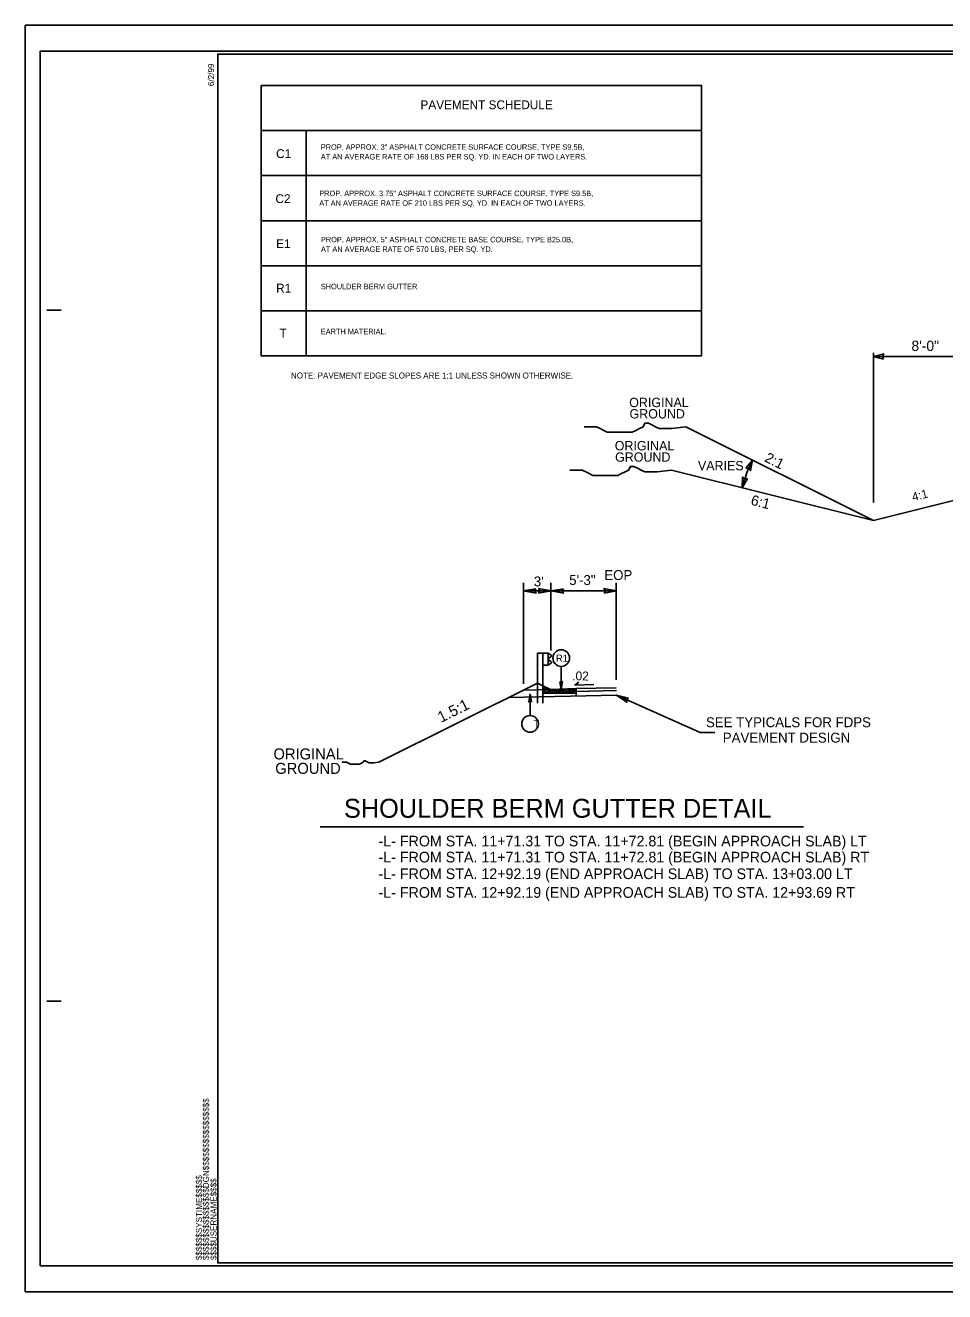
# Model space of a CAD drawing. Extents: x 573980 to 574178, y -53449 to -53334.
# Drawn here: x 573980.1 to 574063.6, y -53449 to -53334 of the extents above; entities that cross this region are included whole.
import ezdxf

# ---------------------------------------------------------------- set-up
doc = ezdxf.new("R2010")
doc.units = 0
for name, color, linetype in [('Old_Level_1', 7, 'Continuous'), ('Old_Level_11', 7, 'Continuous'), ('Prop Conc Shoulder Berm Gutter', 7, 'Continuous'), ('Prop Dimension Text', 7, 'Continuous'), ('Prop Pavement Schedule Description CELL', 7, 'Continuous'), ('Sheet Plot Border Inside CELL', 7, 'Continuous'), ('Sheet Plot Border Outside CELL', 7, 'Continuous'), ('Sheet Typical CELL', 7, 'Continuous'), ('Typical Slope Point Local CELL', 7, 'Continuous'), ('Typical Terminator CELL', 7, 'Continuous'), ('Typical Text General CELL', 7, 'Continuous')]:
    doc.layers.add(name, color=color, linetype=linetype)

# ---------------------------------------------------------------- blocks, each defined once
blk = doc.blocks.new('TERMINATOR')
at = {"layer": 'Typical Terminator CELL'}
blk.add_lwpolyline([(-0.469, 0.081), (0, 0), (-0.471, -0.083), (-0.411, 0)], close=True, dxfattribs=at)

msp = doc.modelspace()

# ---------------------------------------------------------------- linework, layer by layer
at = {"layer": 'Old_Level_1'}
msp.add_line((574006.85, -53406.8), (574050.73, -53406.8), dxfattribs=at)
at = {"layer": 'Prop Conc Shoulder Berm Gutter'}
for p, q in [((574027.06, -53391.01), (574026.59, -53391.01)), ((574026.59, -53391.01), (574026.59, -53393.39)), ((574027.06, -53391.01), (574027.06, -53393.39)), ((574027.06, -53391.01), (574027.54, -53391.01)), ((574027.54, -53391.01), (574027.54, -53392.12)), ((574027.54, -53391.01), (574027.82, -53391.2)), ((574027.54, -53391.52), (574027.82, -53391.33)), ((574027.54, -53391.56), (574027.54, -53391.52)), ((574027.54, -53391.56), (574027.54, -53391.61)), ((574027.54, -53391.61), (574027.82, -53391.8)), ((574027.06, -53392.12), (574027.54, -53392.12)), ((574027.54, -53392.12), (574027.82, -53391.93)), ((574028.74, -53392.23), (574028.74, -53394.32)), ((574012.19, -53400.94), (574026.59, -53393.74)), ((574026.59, -53393.39), (574026.59, -53395.58)), ((574027.06, -53393.98), (574026.59, -53393.74)), ((574027.06, -53393.39), (574027.06, -53395.58)), ((574027.06, -53393.98), (574027.76, -53394.33)), ((574027.06, -53394.66), (574027.06, -53393.98)), ((574029.97, -53393.92), (574030.34, -53393.67)), ((574031.71, -53393.88), (574029.97, -53393.92)), ((574023.99, -53395.05), (574033.76, -53394.83)), ((574025.32, -53394.38), (574027.76, -53394.33)), ((574025.91, -53396.7), (574025.91, -53394.74)), ((574030.09, -53394.66), (574027.06, -53394.66)), ((574027.26, -53394.33), (574027.27, -53394.4)), ((574027.38, -53394.36), (574027.26, -53394.33)), ((574027.27, -53394.4), (574027.38, -53394.36)), ((574027.53, -53394.58), (574027.58, -53394.48)), ((574027.66, -53394.54), (574027.53, -53394.58)), ((574027.58, -53394.48), (574027.66, -53394.54)), ((574030.09, -53394.25), (574027.76, -53394.33)), ((574027.85, -53394.58), (574027.9, -53394.49)), ((574027.99, -53394.55), (574027.85, -53394.58)), ((574027.9, -53394.49), (574027.99, -53394.55)), ((574028.24, -53394.54), (574028.31, -53394.44)), ((574028.34, -53394.53), (574028.24, -53394.54)), ((574028.31, -53394.44), (574028.34, -53394.53)), ((574028.53, -53394.58), (574028.58, -53394.48)), ((574028.66, -53394.54), (574028.53, -53394.58)), ((574028.58, -53394.48), (574028.66, -53394.54)), ((574028.84, -53394.47), (574028.89, -53394.38)), ((574028.97, -53394.44), (574028.84, -53394.47)), ((574028.89, -53394.38), (574028.97, -53394.44)), ((574029.24, -53394.54), (574029.31, -53394.44)), ((574029.34, -53394.53), (574029.24, -53394.54)), ((574029.31, -53394.44), (574029.34, -53394.53)), ((574029.53, -53394.58), (574029.58, -53394.48)), ((574029.66, -53394.54), (574029.53, -53394.58)), ((574029.58, -53394.48), (574029.66, -53394.54)), ((574029.88, -53394.41), (574029.93, -53394.32)), ((574030.02, -53394.38), (574029.88, -53394.41)), ((574029.93, -53394.32), (574030.02, -53394.38)), ((574030.09, -53394.25), (574033.74, -53394.17)), ((574030.09, -53394.25), (574030.09, -53394.66)), ((574030.09, -53394.25), (574030.09, -53394.91)), ((574030.09, -53394.5), (574033.75, -53394.42)), ((574033.76, -53394.83), (574041.34, -53398.22)), ((574042.7, -53398.22), (574041.34, -53398.22))]:
    msp.add_line(p, q, dxfattribs=at)
for points in [[(574026.44, -53385.17), (574025.32, -53385.36), (574026.45, -53385.56), (574026.3, -53385.36)], [(574026.69, -53385.56), (574027.82, -53385.36), (574026.69, -53385.16), (574026.83, -53385.36)], [(574028.94, -53385.17), (574027.82, -53385.36), (574028.95, -53385.56), (574028.81, -53385.36)], [(574032.63, -53385.56), (574033.75, -53385.36), (574032.62, -53385.16), (574032.76, -53385.36)], [(574028.62, -53393.62), (574028.74, -53394.32), (574028.86, -53393.61), (574028.74, -53393.7)], [(574026.03, -53395.44), (574025.91, -53394.74), (574025.79, -53395.45), (574025.91, -53395.36)], [(574034.86, -53395.12), (574033.76, -53394.83), (574034.7, -53395.48), (574034.66, -53395.24)]]:
    msp.add_lwpolyline(points, close=True, dxfattribs=at)
msp.add_lwpolyline([(574012.19, -53400.94), (574011.72, -53401), (574011.6, -53401), (574011.42, -53401), (574011.3, -53401), (574011.19, -53400.94), (574011.07, -53400.88), (574010.95, -53400.82), (574010.83, -53400.82), (574010.77, -53400.94), (574010.65, -53401), (574010.54, -53401.06), (574010.42, -53401.12), (574010.3, -53401.12), (574010.18, -53401.12), (574010.06, -53401.12), (574009.94, -53401.12), (574009.83, -53401.12), (574009.71, -53401.12), (574009.59, -53401.12), (574009.47, -53401.06), (574009.35, -53401), (574009.23, -53400.94), (574009.06, -53400.94), (574008.94, -53400.94), (574008.82, -53400.94)], dxfattribs=at)
for centre, radius in [((574028.74, -53391.47), 0.757), ((574027.12, -53394.07), 0.00643), ((574027.11, -53394.38), 0.00643), ((574027.12, -53394.59), 0.00643), ((574027.13, -53394.22), 0.00643), ((574027.18, -53394.47), 0.00643), ((574027.2, -53394.26), 0.00643), ((574027.2, -53394.34), 0.00643), ((574027.24, -53394.61), 0.00643), ((574027.28, -53394.51), 0.00643), ((574027.29, -53394.16), 0.00643), ((574027.29, -53394.49), 0.00643), ((574027.31, -53394.33), 0.00643), ((574027.31, -53394.45), 0.00643), ((574027.33, -53394.25), 0.00643), ((574027.36, -53394.29), 0.00643), ((574027.38, -53394.6), 0.00643), ((574027.4, -53394.21), 0.00643), ((574027.43, -53394.4), 0.00643), ((574027.46, -53394.63), 0.00643), ((574027.46, -53394.51), 0.00643), ((574027.49, -53394.28), 0.00643), ((574027.51, -53394.39), 0.00643), ((574027.59, -53394.41), 0.00643), ((574027.59, -53394.62), 0.00643), ((574027.62, -53394.31), 0.00643), ((574027.67, -53394.47), 0.00643), ((574027.72, -53394.46), 0.00643), ((574027.73, -53394.38), 0.00643), ((574027.76, -53394.57), 0.00643), ((574027.78, -53394.41), 0.00643), ((574027.81, -53394.34), 0.00643), ((574027.84, -53394.53), 0.00643), ((574027.9, -53394.38), 0.00643), ((574027.94, -53394.37), 0.00643), ((574027.95, -53394.45), 0.00643), ((574027.98, -53394.62), 0.00643), ((574028.05, -53394.46), 0.00643), ((574028.06, -53394.38), 0.00643), ((574028.09, -53394.57), 0.00643), ((574028.1, -53394.41), 0.00643), ((574028.12, -53394.43), 0.00643), ((574028.17, -53394.54), 0.00643), ((574028.16, -53394.62), 0.00643), ((574028.18, -53394.44), 0.00643), ((574028.24, -53394.49), 0.00643), ((574028.27, -53394.38), 0.00643), ((574028.27, -53394.62), 0.00643), ((574028.34, -53394.35), 0.00643), ((574028.34, -53394.47), 0.00643), ((574028.41, -53394.59), 0.00643), ((574028.45, -53394.43), 0.00643), ((574028.47, -53394.36), 0.00643), ((574028.48, -53394.52), 0.00643), ((574028.58, -53394.38), 0.00643), ((574028.59, -53394.62), 0.00643), ((574028.67, -53394.47), 0.00643), ((574028.71, -53394.32), 0.00643), ((574028.72, -53394.46), 0.00643), ((574028.73, -53394.38), 0.00643), ((574028.76, -53394.57), 0.00643), ((574028.78, -53394.41), 0.00643), ((574028.83, -53394.35), 0.00643), ((574028.84, -53394.53), 0.00643), ((574028.86, -53394.63), 0.00643), ((574028.93, -53394.51), 0.00643), ((574028.96, -53394.31), 0.00643), ((574028.98, -53394.62), 0.00643), ((574029.01, -53394.54), 0.00643), ((574029.05, -53394.46), 0.00643), ((574029.06, -53394.38), 0.00643), ((574029.09, -53394.57), 0.00643), ((574029.1, -53394.41), 0.00643), ((574029.12, -53394.43), 0.00643), ((574029.11, -53394.62), 0.00643), ((574029.16, -53394.31), 0.00643), ((574029.17, -53394.54), 0.00643), ((574029.24, -53394.49), 0.00643), ((574029.26, -53394.36), 0.00643), ((574029.27, -53394.38), 0.00643), ((574029.27, -53394.62), 0.00643), ((574029.34, -53394.47), 0.00643), ((574029.35, -53394.3), 0.00643), ((574029.36, -53394.62), 0.00643), ((574029.42, -53394.35), 0.00643), ((574029.43, -53394.53), 0.00643), ((574029.45, -53394.43), 0.00643), ((574029.51, -53394.48), 0.00643), ((574029.5, -53394.6), 0.00643), ((574029.58, -53394.38), 0.00643), ((574029.59, -53394.36), 0.00643), ((574029.59, -53394.62), 0.00643), ((574029.65, -53394.29), 0.00643), ((574029.67, -53394.47), 0.00643), ((574029.68, -53394.61), 0.00643), ((574029.72, -53394.46), 0.00643), ((574029.73, -53394.38), 0.00643), ((574029.74, -53394.29), 0.00643), ((574029.77, -53394.57), 0.00643), ((574029.78, -53394.41), 0.00643), ((574029.81, -53394.34), 0.00643), ((574029.84, -53394.53), 0.00643), ((574029.88, -53394.46), 0.00643), ((574029.89, -53394.28), 0.00643), ((574029.9, -53394.59), 0.00643), ((574029.97, -53394.5), 0.00643), ((574030.04, -53394.28), 0.00643), ((574030.04, -53394.61), 0.00643), ((574030.05, -53394.46), 0.00643), ((574030.06, -53394.38), 0.00643), ((574025.91, -53397.45), 0.757)]:
    msp.add_circle(centre, radius, dxfattribs=at)
for centre, radius, start, end in [((574027.78, -53391.26), 0.0743, 304.9888, 54.997), ((574027.78, -53391.86), 0.0743, 304.9634, 54.9941), ((574027.16, -53394.18), 0.00643, 311.0057, 48.9943), ((574027.78, -53394.66), 0.00643, 49.2889, 130.7111), ((574028.1, -53394.34), 0.00643, 209.9612, 270.0259), ((574028.26, -53394.36), 0.00643, 208.3343, 333.6652), ((574028.45, -53394.66), 0.00643, 21.9976, 158.0024), ((574028.59, -53394.36), 0.00643, 126.5832, 55.4163), ((574028.78, -53394.66), 0.00643, 49.2889, 130.7111), ((574029.1, -53394.34), 0.00643, 190.5183, 351.4812), ((574029.45, -53394.66), 0.00643, 21.9976, 158.0024), ((574029.48, -53394.34), 0.00643, 172.1997, 9.7998), ((574029.78, -53394.66), 0.00643, 49.2889, 130.7111), ((574030.09, -53394.57), 0.00643, 127.9938, 232.0062)]:
    msp.add_arc(centre, radius, start, end, dxfattribs=at)
at = {"layer": 'Prop Dimension Text'}
for p, q in [((574057.08, -53377.35), (574057.08, -53363.73)), ((574057.08, -53364.07), (574106.45, -53364.07)), ((574025.32, -53393.8), (574025.32, -53384.64)), ((574027.8, -53390.79), (574027.8, -53384.64)), ((574033.74, -53393.45), (574033.74, -53384.64)), ((574025.32, -53385.36), (574027.82, -53385.36)), ((574033.75, -53385.36), (574027.82, -53385.36))]:
    msp.add_line(p, q, dxfattribs=at)
msp.add_arc((574057.08, -53378.97), 12.27, 153.4349, 165.9638, dxfattribs=at)
at = {"layer": 'Prop Pavement Schedule Description CELL'}
msp.add_line((574001.48, -53364.01), (574001.48, -53364.01), dxfattribs=at)
msp.add_lwpolyline([(574001.48, -53339.46), (574041.48, -53339.46), (574041.48, -53343.55), (574001.48, -53343.55)], close=True, dxfattribs=at)
for points in [[(574005.57, -53347.64), (574001.48, -53347.64), (574001.48, -53343.55), (574041.48, -53343.55), (574041.48, -53347.64), (574005.57, -53347.64), (574005.57, -53343.55)], [(574005.57, -53351.74), (574001.48, -53351.74), (574001.48, -53347.64), (574041.48, -53347.64), (574041.48, -53351.74), (574005.57, -53351.74), (574005.57, -53347.64)], [(574005.57, -53355.83), (574001.48, -53355.83), (574001.48, -53351.74), (574041.48, -53351.74), (574041.48, -53355.83), (574005.57, -53355.83), (574005.57, -53351.74)], [(574005.57, -53359.92), (574001.48, -53359.92), (574001.48, -53355.83), (574041.48, -53355.83), (574041.48, -53359.92), (574005.57, -53359.92), (574005.57, -53355.83)], [(574005.57, -53364.01), (574001.48, -53364.01), (574001.48, -53359.92), (574041.48, -53359.92), (574041.48, -53364.01), (574005.57, -53364.01), (574005.57, -53359.92)]]:
    msp.add_lwpolyline(points, dxfattribs=at)
at = {"layer": 'Sheet Plot Border Inside CELL'}
msp.add_lwpolyline([(574155.75, -53336.33), (573981.44, -53336.33), (573981.44, -53446.69), (574155.75, -53446.69)], close=True, dxfattribs=at)
at = {"layer": 'Sheet Plot Border Outside CELL'}
msp.add_lwpolyline([(574156.22, -53333.98), (573980.08, -53333.98), (573980.08, -53449.04), (574156.22, -53449.04)], close=True, dxfattribs=at)
at = {"layer": 'Sheet Typical CELL'}
for p, q in [((573982.02, -53359.87), (573983.32, -53359.87)), ((573982.02, -53422.63), (573983.32, -53422.63)), ((573997.55, -53446.42), (573997.55, -53446.42)), ((573997.55, -53446.42), (573997.55, -53446.42)), ((573997.55, -53446.42), (573997.55, -53446.42)), ((573997.55, -53446.42), (573997.55, -53446.42)), ((573997.55, -53446.42), (573997.55, -53446.42)), ((573997.55, -53446.42), (573997.55, -53446.42))]:
    msp.add_line(p, q, dxfattribs=at)
msp.add_lwpolyline([(574154.44, -53336.6), (573997.55, -53336.6), (573997.55, -53446.42), (574154.44, -53446.42)], close=True, dxfattribs=at)
msp.add_lwpolyline([(574001.47, -53446.42), (574001.47, -53446.42)], dxfattribs=at)
at = {"layer": 'Typical Slope Point Local CELL'}
for p in [(574040.06, -53370.46), (574038.75, -53374.39), (574067.08, -53376.47)]:
    msp.add_line(p, (574057.08, -53378.97), dxfattribs=at)
for points in [[(574040.06, -53370.46), (574038.76, -53370.62), (574038.44, -53370.62), (574037.95, -53370.62), (574037.63, -53370.62), (574037.3, -53370.46), (574036.98, -53370.29), (574036.65, -53370.13), (574036.33, -53370.13), (574036.17, -53370.46), (574035.84, -53370.62), (574035.52, -53370.78), (574035.19, -53370.94), (574034.87, -53370.94), (574034.55, -53370.94), (574034.22, -53370.94), (574033.9, -53370.94), (574033.57, -53370.94), (574033.25, -53370.94), (574032.92, -53370.94), (574032.6, -53370.78), (574032.28, -53370.62), (574031.95, -53370.46), (574031.47, -53370.46), (574031.14, -53370.46), (574030.82, -53370.46)], [(574038.75, -53374.39), (574037.45, -53374.55), (574037.13, -53374.55), (574036.64, -53374.55), (574036.32, -53374.55), (574035.99, -53374.39), (574035.67, -53374.22), (574035.34, -53374.06), (574035.02, -53374.06), (574034.86, -53374.39), (574034.53, -53374.55), (574034.21, -53374.71), (574033.88, -53374.87), (574033.56, -53374.87), (574033.24, -53374.87), (574032.91, -53374.87), (574032.59, -53374.87), (574032.26, -53374.87), (574031.94, -53374.87), (574031.61, -53374.87), (574031.29, -53374.71), (574030.97, -53374.55), (574030.64, -53374.39), (574030.16, -53374.39), (574029.83, -53374.39), (574029.51, -53374.39)]]:
    msp.add_lwpolyline(points, dxfattribs=at)

# ---------------------------------------------------------------- block references
at = {"layer": 'Old_Level_11'}
for p, xscale, yscale, rotation in [((574057.08, -53364.07), 1.9883351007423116, 2.853881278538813, 180), ((574046.11, -53373.48), 1.9883351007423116, 2.853881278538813, 65.2036293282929), ((574045.18, -53375.99), 1.9883351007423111, 2.853881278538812, -106.02476566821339)]:
    msp.add_blockref('TERMINATOR', p, dxfattribs=dict(at, xscale=xscale, yscale=yscale, rotation=rotation))

# ---------------------------------------------------------------- texts
at = {"layer": 'Old_Level_1'}
for s, p in [('ORIGINAL ', (574034.91, -53368.67)), ('GROUND', (574034.94, -53369.7)), ('ORIGINAL ', (574033.6, -53372.6)), ('GROUND', (574033.63, -53373.63)), ('VARIES', (574041.15, -53374.41))]:
    msp.add_text(s, height=0.846, dxfattribs=at).set_placement(p)
at = {"layer": 'Prop Conc Shoulder Berm Gutter'}
for s, height, p in [('R1', 0.65, (574028.25, -53391.81)), ('SEE TYPICALS FOR FDPS ', 0.9, (574041.88, -53397.75)), ('PAVEMENT DESIGN', 0.9, (574043.41, -53399.15)), ('ORIGINAL', 1, (574002.61, -53400.68)), ('GROUND', 1, (574002.77, -53401.99)), ('SHOULDER BERM GUTTER DETAIL', 1.719, (574009.01, -53405.98)), ('-L- FROM STA. 11+71.31 TO STA. 11+72.81 (BEGIN APPROACH SLAB) LT', 0.9669, (574012.15, -53408.58)), ('-L- FROM STA. 11+71.31 TO STA. 11+72.81 (BEGIN APPROACH SLAB) RT', 0.9669, (574012.15, -53410.04)), ('-L- FROM STA. 12+92.19 (END APPROACH SLAB) TO STA. 13+03.00 LT', 0.9669, (574012.15, -53411.55)), ('-L- FROM STA. 12+92.19 (END APPROACH SLAB) TO STA. 12+93.69 RT', 0.9669, (574012.15, -53413.25))]:
    msp.add_text(s, height=height, dxfattribs=at).set_placement(p)
for s, height, rotation, p in [('.02', 0.81, 358.7448, (574029.73, -53393.48)), ('1.5:1', 1, 26.5651, (574017.83, -53397.36)), ('T', 0.65, 360, (574026.21, -53397.75))]:
    msp.add_text(s, height=height, rotation=rotation, dxfattribs=at).set_placement(p)
at = {"layer": 'Prop Dimension Text'}
for s, height, p in [('8\'-0"', 0.938, (574060.54, -53363.57)), ('EOP', 0.9, (574032.65, -53384.38)), ("3'", 0.9, (574026.25, -53384.96)), ('5\'-3"', 0.9, (574029.46, -53384.83))]:
    msp.add_text(s, height=height, dxfattribs=at).set_placement(p)
at = {"layer": 'Prop Pavement Schedule Description CELL'}
for s, height, p in [('PAVEMENT SCHEDULE', 0.8, (574015.96, -53341.6)), ('C1', 0.8, (574002.85, -53346.04)), ('AT AN AVERAGE RATE OF 168 LBS PER SQ. YD. IN EACH OF TWO LAYERS.', 0.5, (574006.91, -53346.17)), ('PROP. APPROX. 3" ASPHALT CONCRETE SURFACE COURSE, TYPE S9.5B,', 0.5, (574006.91, -53345.29)), ('PROP. APPROX. 3.75" ASPHALT CONCRETE SURFACE COURSE, TYPE S9.5B,', 0.5, (574006.77, -53349.5)), ('C2', 0.8, (574002.79, -53350.13)), ('AT AN AVERAGE RATE OF 210 LBS PER SQ. YD. IN EACH OF TWO LAYERS.', 0.5, (574006.77, -53350.38)), ('E1', 0.8, (574002.85, -53354.22)), ('PROP. APPROX. 5" ASPHALT CONCRETE BASE COURSE, TYPE B25.0B,', 0.5, (574006.92, -53353.7)), ('AT AN AVERAGE RATE OF 570 LBS, PER SQ. YD.', 0.5, (574006.92, -53354.57)), ('R1', 0.8, (574002.85, -53358.26)), ('SHOULDER BERM GUTTER', 0.5, (574006.91, -53357.96)), ('T', 0.8, (574003.16, -53362.35)), ('EARTH MATERIAL.', 0.5, (574006.91, -53362.05)), ('NOTE: PAVEMENT EDGE SLOPES ARE 1:1 UNLESS SHOWN OTHERWISE.', 0.5442, (574004.2, -53366.07))]:
    msp.add_text(s, height=height, dxfattribs=at).set_placement(p)
at = {"layer": 'Sheet Typical CELL'}
for s, height, p in [('6/2/99', 0.549, (573997.22, -53339.5)), ('$$$$$$$$$$$$$$$$DGN$$$$$$$$$$$$$$$$', 0.5491, (573996.75, -53446.17)), ('$$$$$$SYSTIME$$$$$', 0.5491, (573996.12, -53446.17)), ('$$$$USERNAME$$$$', 0.5491, (573997.44, -53446.17))]:
    msp.add_text(s, height=height, rotation=90, dxfattribs=at).set_placement(p)
at = {"layer": 'Typical Slope Point Local CELL'}
msp.add_text('4:1', height=0.781, rotation=14.0362, dxfattribs=at).set_placement((574060.69, -53377.23))
at = {"layer": 'Typical Text General CELL'}
for s, rotation, p in [('2:1', 333.4349, (574047.13, -53373.57)), ('6:1', 345.7105, (574045.89, -53377.53))]:
    msp.add_text(s, height=0.932, rotation=rotation, dxfattribs=at).set_placement(p)

doc.saveas('drawing.dxf')
